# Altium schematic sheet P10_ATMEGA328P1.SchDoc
size A4; SheetNumber: 2; SheetTotal: 2
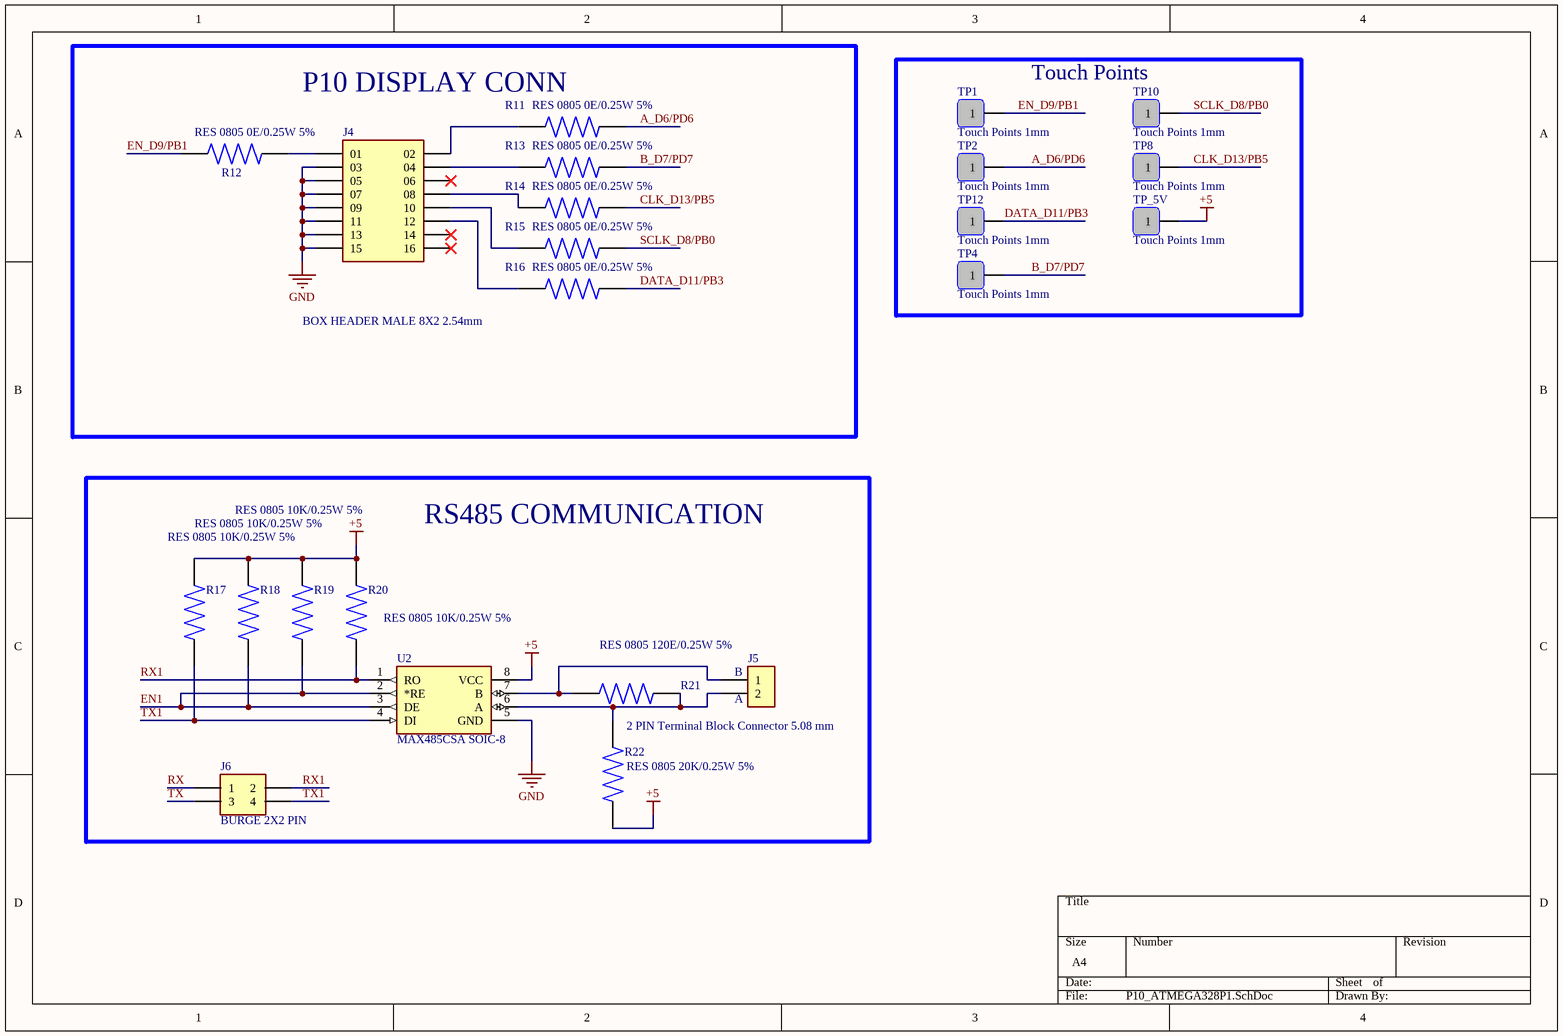
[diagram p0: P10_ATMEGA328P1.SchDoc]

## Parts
J4  BOX HEADER MALE 8X2 2.54mm  [BOX HEADER MALE 8X2 2.54mm]
J5  2 PIN Terminal Block Connector 5.08 mm  [2 PIN Terminal Block Connector 5.08 mm]
J6  BURGE 2X2 PIN  [BURGE 2X2 pin]
R11  RES 0805 0E/0.25W 5%  [RES 0805 10K/0.25W 5%]
R12  RES 0805 0E/0.25W 5%  [RES 0805 10K/0.25W 5%]
R13  RES 0805 0E/0.25W 5%  [RES 0805 10K/0.25W 5%]
R14  RES 0805 0E/0.25W 5%  [RES 0805 10K/0.25W 5%]
R15  RES 0805 0E/0.25W 5%  [RES 0805 10K/0.25W 5%]
R16  RES 0805 0E/0.25W 5%  [RES 0805 10K/0.25W 5%]
R17  RES 0805 10K/0.25W 5%  [RES 0805 10K/0.25W 5%]
R18  RES 0805 10K/0.25W 5%  [RES 0805 10K/0.25W 5%]
R19  RES 0805 10K/0.25W 5%  [RES 0805 10K/0.25W 5%]
R20  RES 0805 10K/0.25W 5%  [RES 0805 10K/0.25W 5%]
R21  RES 0805 120E/0.25W 5%  [RES 0805 10K/0.25W 5%]
R22  RES 0805 20K/0.25W 5%  [RES 0805 10K/0.25W 5%]
TP1  Touch Points 1mm  [Touch Points 1mm]
TP2  Touch Points 1mm  [Touch Points 1mm]
TP4  Touch Points 1mm  [Touch Points 1mm]
TP8  Touch Points 1mm  [Touch Points 1mm]
TP10  Touch Points 1mm  [Touch Points 1mm]
TP12  Touch Points 1mm  [Touch Points 1mm]
TP_5V  Touch Points 1mm  [Touch Points 1mm]
U2  MAX485CSA SOIC-8  [MAX485CSA]

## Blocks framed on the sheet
P10 DISPLAY CONN: J4 R11-R16
Touch Points: TP1 TP2 TP4 TP8 TP10 TP12 TP_5V
RS485 COMMUNICATION: J5 J6 R17-R22 U2

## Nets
+5: R17.2 R18.2 R19.2 R20.2 R22.1 TP_5V.1 U2.8(VCC)
GND: J4.03 J4.05 J4.07 J4.09 J4.11 J4.13 J4.15 U2.5(GND)
A_D6/PD6: R11.2 TP2.1
B_D7/PD7: R13.2 TP4.1
CLK_D13/PB5: R14.2 TP8.1
DATA_D11/PB3: R16.2 TP12.1
EN1: R18.1 R19.1 U2.2(*RE) U2.3(DE)
EN_D9/PB1: R12.1 TP1.1
RX: J6.01(1)
RX1: J6.02(2) R20.1 U2.1(RO)
SCLK_D8/PB0: R15.2 TP10.1
TX: J6.03(3)
TX1: J6.04(4) R17.1 U2.4(DI)
NetJ4_01: J4.01 R12.2
NetJ4_02: J4.02 R11.1
NetJ4_04: J4.04 R13.1
NetJ4_08: J4.08 R14.1
NetJ4_10: J4.10 R15.1
NetJ4_12: J4.12 R16.1
NetJ5_1: J5.1 R21.1 U2.7(B)
NetJ5_2: J5.2 R21.2 R22.2 U2.6(A)

Not connected (* = marked no-connect by the designer): J4 06* 14* 16*

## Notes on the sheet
- (near J5) A
- (near J5) B

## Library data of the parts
J4 = BOX HEADER MALE 8X2 2.54mm: BOX HEADER MALE 8X2 2.54mm 16 pin; MP: TSS-108-01-T-D
J5 = 2 PIN Terminal Block Connector 5.08 mm: MOLEX,Screw Type, Horizontal, 5.08 Pitch, 24~12 (AWG), Terminal Block Connector, TB007-508-02BE; MF: Same Sky
J6 = 4PIN BURGE: Connector Header Through Hole 4 position 0.100 (2.54mm), 2X2 PIN; MF: Samtec; MP: MTLW-102-05-G-D-180
R11-R22 = RES 0805 10K/0.25W 5%: RESISTOR, THICK FILM, 10K, 5%, 0805, FRESISTOR, THICK FILM, 10K, 5%, 0805, FULL REEL Product Range:PANASONIC - ERJ Series; MP: ERJ-6GEYJ103V; MF: Panasonic Electronic
TP1 TP2 TP4 TP8 TP10 TP12 TP_5V = Touch Points: Touch Points 0.75mm to1mm
U2 = MAX485CSA: MAX485CSA-RS-485/RS-422 Transceivers, SOIC-8; MF: Analog Devices; MP: MAX485CSA+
